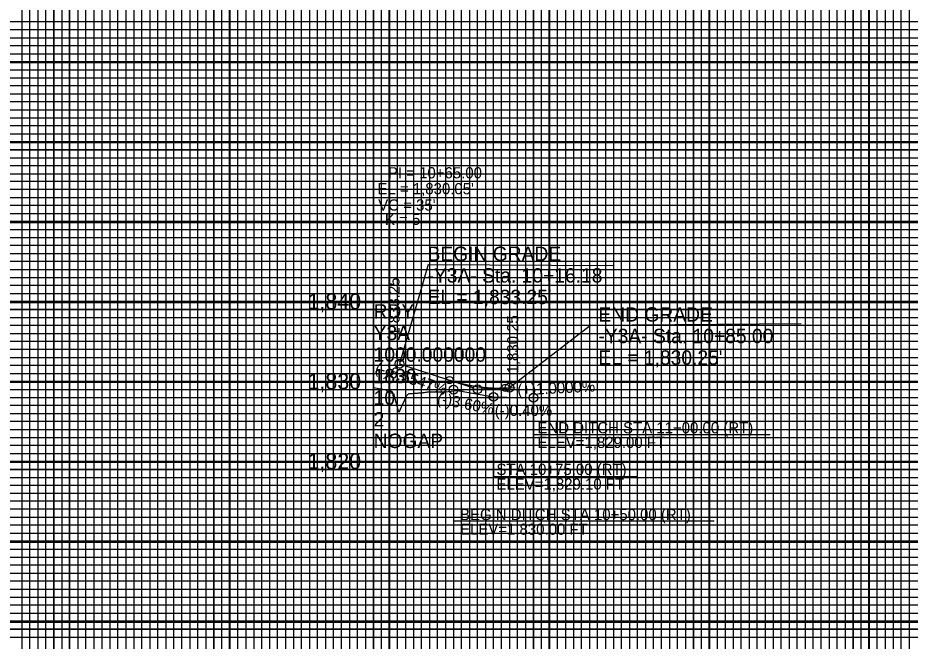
# Model space of a CAD drawing. Extents: x 553912 to 567693, y 512355 to 537539.
# Drawn here: x 560417 to 560975, y 521343 to 521733 of the extents above; entities that cross this region are included whole.
import ezdxf

# ---------------------------------------------------------------- set-up
doc = ezdxf.new("R2010")
doc.units = 0
for name, color, linetype in [('Exist Profile Cell', 7, 'Continuous'), ('Exist Vertical Profile Ground Line', 7, 'Continuous'), ('Exist Vertical Profile Vertical Axis Label', 7, 'Continuous'), ('Old_Level_42', 7, 'Continuous'), ('Old_Level_54', 7, 'Continuous'), ('Prop ROW Permanent Easement CELL', 7, 'Continuous'), ('Prop Vertical Profile Curve Label', 7, 'Continuous'), ('Prop Vertical Profile Ditch Grade Right', 7, 'Continuous'), ('Prop Vertical Profile Ditch Grade Right Label', 7, 'Continuous'), ('Prop Vertical Profile Grade', 7, 'Continuous'), ('Prop Vertical Profile Grade Label', 7, 'Continuous'), ('Prop VPI Label', 7, 'Continuous'), ('Sheet Profile Grid Major CELL', 7, 'Continuous'), ('Sheet Summary Guardrail CELL', 7, 'Continuous')]:
    doc.layers.add(name, color=color, linetype=linetype)

msp = doc.modelspace()

# ---------------------------------------------------------------- linework, layer by layer
at = {"layer": 'Exist Profile Cell'}
for q in [(560639.69, 521700.27), (560728.24, 521450.27), (560639.69, 521450.27)]:
    msp.add_line((560639.69, 521450.27), q, dxfattribs=at)
at = {"layer": 'Exist Vertical Profile Ground Line'}
msp.add_lwpolyline([(560639.69, 521501.61), (560645.54, 521500.52), (560647.01, 521500.28), (560648.88, 521498.77), (560652.04, 521497.86), (560655.11, 521487.07), (560655.61, 521486.15), (560656.47, 521488.01), (560657.15, 521489.49), (560657.83, 521490.97), (560658.5, 521492.45), (560659.18, 521493.93), (560659.86, 521495.41), (560660.54, 521496.6), (560661.59, 521497.76), (560661.9, 521497.79), (560662.58, 521497.84), (560663.26, 521497.9), (560663.94, 521497.95), (560664.62, 521498), (560665.3, 521498.05), (560665.97, 521498.1), (560666.65, 521498.15), (560667.33, 521498.19), (560668.01, 521498.24), (560668.69, 521498.28), (560669.37, 521498.32), (560670.34, 521498.38), (560670.73, 521498.44), (560671.41, 521498.55), (560672.09, 521498.66), (560672.76, 521498.77), (560673.44, 521498.88), (560674.12, 521498.97), (560674.8, 521498.98), (560675.48, 521498.98), (560676.16, 521498.98), (560676.84, 521498.98), (560677.52, 521498.98), (560678.2, 521498.98), (560678.88, 521498.98), (560679.56, 521498.98), (560680.23, 521498.98), (560680.91, 521498.98), (560681.59, 521498.98), (560682.27, 521498.98), (560682.95, 521498.98), (560683.63, 521498.98), (560684.44, 521498.97), (560699.56, 521500.58), (560700.04, 521500.58), (560700.64, 521500.64), (560710.34, 521500.79), (560717.31, 521500.81), (560717.75, 521500.78), (560718.51, 521500.82), (560728.24, 521501.54)], dxfattribs=at)
at = {"layer": 'Old_Level_42'}
for p, q in [((560439.66, 522125.42), (560439.66, 521100.42)), ((560489.66, 522125.42), (560489.66, 521100.42)), ((560539.66, 522125.42), (560539.66, 521100.42)), ((560589.66, 522125.42), (560589.66, 521100.42)), ((560639.66, 522125.42), (560639.66, 521100.42)), ((560689.66, 522125.42), (560689.66, 521100.42)), ((560739.66, 522125.42), (560739.66, 521100.42)), ((560789.66, 522125.42), (560789.66, 521100.42)), ((560839.66, 522125.42), (560839.66, 521100.42)), ((560889.66, 522125.42), (560889.66, 521100.42)), ((560939.66, 522125.42), (560939.66, 521100.42)), ((559939.66, 521700.42), (561439.66, 521700.42)), ((559939.66, 521650.42), (561439.66, 521650.42)), ((559939.66, 521600.42), (561439.66, 521600.42)), ((559939.66, 521550.42), (561439.66, 521550.42)), ((559939.66, 521500.42), (561439.66, 521500.42)), ((559939.66, 521450.42), (561439.66, 521450.42)), ((559939.66, 521400.42), (561439.66, 521400.42)), ((559939.66, 521350.42), (561439.66, 521350.42))]:
    msp.add_line(p, q, dxfattribs=at)
at = {"layer": 'Old_Level_54'}
for points in [[(560389.66, 522125.42), (560389.66, 521100.42), (560439.66, 521100.42), (560439.66, 522125.42)], [(560489.66, 522125.42), (560489.66, 521100.42), (560539.66, 521100.42), (560539.66, 522125.42)], [(560589.66, 522125.42), (560589.66, 521100.42), (560639.66, 521100.42), (560639.66, 522125.42)], [(560689.66, 522125.42), (560689.66, 521100.42), (560739.66, 521100.42), (560739.66, 522125.42)], [(560789.66, 522125.42), (560789.66, 521100.42), (560839.66, 521100.42), (560839.66, 522125.42)], [(560889.66, 522125.42), (560889.66, 521100.42), (560939.66, 521100.42), (560939.66, 522125.42)], [(561439.66, 521650.42), (559939.66, 521650.42), (559939.66, 521700.42), (561439.66, 521700.42)], [(561439.66, 521550.42), (559939.66, 521550.42), (559939.66, 521600.42), (561439.66, 521600.42)], [(561439.66, 521450.42), (559939.66, 521450.42), (559939.66, 521500.42), (561439.66, 521500.42)], [(561439.66, 521350.42), (559939.66, 521350.42), (559939.66, 521400.42), (561439.66, 521400.42)]]:
    msp.add_lwpolyline(points, dxfattribs=at)
at = {"layer": 'Prop ROW Permanent Easement CELL'}
for points in [[(560464.66, 522125.42), (560464.66, 521100.42), (560514.66, 521100.42), (560514.66, 522125.42)], [(560564.66, 522125.42), (560564.66, 521100.42), (560614.66, 521100.42), (560614.66, 522125.42)], [(560664.66, 522125.42), (560664.66, 521100.42), (560714.66, 521100.42), (560714.66, 522125.42)], [(560764.66, 522125.42), (560764.66, 521100.42), (560814.66, 521100.42), (560814.66, 522125.42)], [(560864.66, 522125.42), (560864.66, 521100.42), (560914.66, 521100.42), (560914.66, 522125.42)], [(560964.66, 522125.42), (560964.66, 521100.42), (561014.66, 521100.42)], [(561439.66, 521725.42), (559939.66, 521725.42), (559939.66, 521675.42), (561439.66, 521675.42)], [(561439.66, 521625.42), (559939.66, 521625.42), (559939.66, 521575.42), (561439.66, 521575.42)], [(561439.66, 521525.42), (559939.66, 521525.42), (559939.66, 521475.42), (561439.66, 521475.42)], [(561439.66, 521425.42), (559939.66, 521425.42), (559939.66, 521375.42), (561439.66, 521375.42)]]:
    msp.add_lwpolyline(points, dxfattribs=at)
at = {"layer": 'Prop Vertical Profile Curve Label'}
for centre in [(560687.19, 521506.26), (560722.19, 521501.4)]:
    msp.add_circle(centre, 2.25, dxfattribs=at)
at = {"layer": 'Prop Vertical Profile Ditch Grade Right'}
for p, q in [((560689.69, 521500.27), (560714.69, 521495.77)), ((560714.69, 521495.77), (560739.69, 521495.27))]:
    msp.add_line(p, q, dxfattribs=at)
at = {"layer": 'Prop Vertical Profile Ditch Grade Right Label'}
for p, q in [((560689.69, 521500.27), (560689.69, 521417.93)), ((560714.69, 521495.77), (560714.69, 521445.98)), ((560739.69, 521495.27), (560739.69, 521472.15)), ((560739.69, 521472.15), (560887.67, 521472.15)), ((560714.69, 521445.98), (560804.33, 521445.98)), ((560852.76, 521417.93), (560689.69, 521417.93))]:
    msp.add_line(p, q, dxfattribs=at)
for centre in [(560689.69, 521500.27), (560714.69, 521495.77), (560739.69, 521495.27)]:
    msp.add_circle(centre, 2.75, dxfattribs=at)
at = {"layer": 'Prop Vertical Profile Grade'}
for p, q in [((560655.87, 521516.52), (560687.19, 521506.26)), ((560722.19, 521501.4), (560724.69, 521501.52))]:
    msp.add_line(p, q, dxfattribs=at)
msp.add_spline([(560687.19, 521506.26), (560687.89, 521506.03), (560688.59, 521505.81), (560689.29, 521505.59), (560689.99, 521505.38), (560690.69, 521505.18), (560691.39, 521504.98), (560692.09, 521504.78), (560692.79, 521504.59), (560693.49, 521504.41), (560694.19, 521504.23), (560694.89, 521504.06), (560695.59, 521503.89), (560696.29, 521503.72), (560696.99, 521503.57), (560697.69, 521503.41), (560698.39, 521503.27), (560699.09, 521503.12), (560699.79, 521502.99), (560700.49, 521502.85), (560701.19, 521502.73), (560701.89, 521502.61), (560702.59, 521502.49), (560703.29, 521502.38), (560703.99, 521502.28), (560704.69, 521502.18), (560705.39, 521502.08), (560706.09, 521501.99), (560706.79, 521501.91), (560707.49, 521501.83), (560708.19, 521501.76), (560708.89, 521501.69), (560709.59, 521501.63), (560710.29, 521501.57), (560710.99, 521501.52), (560711.69, 521501.47), (560712.39, 521501.43), (560713.09, 521501.39), (560713.79, 521501.36), (560714.49, 521501.33), (560715.19, 521501.31), (560715.89, 521501.3), (560716.59, 521501.29), (560717.29, 521501.28), (560717.99, 521501.28), (560718.69, 521501.29), (560719.39, 521501.3), (560720.09, 521501.32), (560720.79, 521501.34), (560721.49, 521501.37), (560722.19, 521501.4)], degree=3, dxfattribs=at)
at = {"layer": 'Prop VPI Label'}
for p, q in [((560673.7, 521578.64), (560655.87, 521516.52)), ((560673.7, 521578.64), (560789.51, 521577.88)), ((560775.27, 521540.37), (560724.69, 521501.52)), ((560907.12, 521541.51), (560775.27, 521540.37)), ((560687.19, 521506.26), (560702.07, 521501.38)), ((560722.19, 521501.4), (560707.43, 521500.66))]:
    msp.add_line(p, q, dxfattribs=at)
for centre in [(560655.87, 521516.52), (560704.69, 521500.52), (560724.69, 521501.52)]:
    msp.add_circle(centre, 2.75, dxfattribs=at)
at = {"layer": 'Sheet Profile Grid Major CELL'}
for p, q in [((560449.45, 521054.67), (560449.45, 522254.67)), ((560549.45, 521054.67), (560549.45, 522254.67)), ((560649.45, 521054.67), (560649.45, 522254.67)), ((560749.45, 521054.67), (560749.45, 522254.67)), ((560849.45, 521054.67), (560849.45, 522254.67)), ((560949.45, 521054.67), (560949.45, 522254.67)), ((563849.45, 521704.67), (557249.45, 521704.67)), ((563849.45, 521654.67), (557249.45, 521654.67)), ((563849.45, 521604.67), (557249.45, 521604.67)), ((563849.45, 521554.67), (557249.45, 521554.67)), ((563849.45, 521504.67), (557249.45, 521504.67)), ((563849.45, 521454.67), (557249.45, 521454.67)), ((563849.45, 521404.67), (557249.45, 521404.67)), ((563849.45, 521354.67), (557249.45, 521354.67))]:
    msp.add_line(p, q, dxfattribs=at)
at = {"layer": 'Sheet Summary Guardrail CELL'}
for points in [[(560419.66, 522125.42), (560419.66, 521100.42), (560424.66, 521100.42), (560424.66, 522125.42)], [(560429.66, 522125.42), (560429.66, 521100.42), (560434.66, 521100.42), (560434.66, 522125.42)], [(560444.66, 522125.42), (560444.66, 521100.42), (560449.66, 521100.42), (560449.66, 522125.42)], [(560454.66, 522125.42), (560454.66, 521100.42), (560459.66, 521100.42), (560459.66, 522125.42)], [(560469.66, 522125.42), (560469.66, 521100.42)], [(560474.66, 522125.42), (560474.66, 521100.42), (560479.66, 521100.42), (560479.66, 522125.42), (560484.66, 522125.42), (560484.66, 521100.42), (560494.66, 521100.42), (560494.66, 522125.42), (560499.66, 522125.42), (560499.66, 521100.42), (560504.66, 521100.42), (560504.66, 522125.42), (560509.66, 522125.42), (560509.66, 521100.42)], [(560519.66, 521100.42), (560519.66, 522125.42)], [(560524.66, 522125.42), (560524.66, 521100.42), (560529.66, 521100.42), (560529.66, 522125.42)], [(560534.66, 522125.42), (560534.66, 521100.42), (560544.66, 521100.42), (560544.66, 522125.42)], [(560549.66, 522125.42), (560549.66, 521100.42), (560549.66, 521100.42), (560554.66, 521100.42), (560554.66, 522125.42)], [(560559.66, 522125.42), (560559.66, 521100.42), (560569.66, 521100.42), (560569.66, 522125.42)], [(560574.66, 522125.42), (560574.66, 521100.42), (560579.66, 521100.42), (560579.66, 522125.42)], [(560584.66, 522125.42), (560584.66, 521100.42), (560594.66, 521100.42), (560594.66, 522125.42)], [(560599.66, 522125.42), (560599.66, 521100.42), (560604.66, 521100.42), (560604.66, 522125.42)], [(560609.66, 522125.42), (560609.66, 521100.42), (560619.66, 521100.42), (560619.66, 522125.42)], [(560624.66, 522125.42), (560624.66, 521100.42), (560629.66, 521100.42), (560629.66, 522125.42)], [(560634.66, 522125.42), (560634.66, 521100.42), (560644.66, 521100.42), (560644.66, 522125.42)], [(560649.66, 522125.42), (560649.66, 521100.42), (560654.66, 521100.42), (560654.66, 522125.42)], [(560659.66, 522125.42), (560659.66, 521100.42), (560669.66, 521100.42), (560669.66, 522125.42)], [(560674.66, 522125.42), (560674.66, 521100.42), (560679.66, 521100.42), (560679.66, 522125.42)], [(560684.66, 522125.42), (560684.66, 521100.42), (560694.66, 521100.42), (560694.66, 522125.42)], [(560699.66, 522125.42), (560699.66, 521100.42)], [(560709.66, 522124.82), (560709.66, 521100.42), (560719.66, 521100.42), (560719.66, 522125.42)], [(560724.66, 522125.42), (560724.66, 521100.42), (560729.66, 521100.42), (560729.66, 522125.42)], [(560734.66, 522125.42), (560734.66, 521100.42), (560744.66, 521100.42), (560744.66, 522125.42)], [(560749.66, 522125.42), (560749.66, 521100.42), (560754.66, 521100.42), (560754.66, 522125.42)], [(560759.66, 522125.42), (560759.66, 521100.42), (560769.66, 521100.42), (560769.66, 522125.42)], [(560774.66, 522125.42), (560774.66, 521100.42), (560779.66, 521100.42), (560779.66, 522125.42)], [(560784.66, 522125.42), (560784.66, 521100.42), (560794.66, 521100.42), (560794.66, 522125.42)], [(560799.66, 522125.42), (560799.66, 521100.42), (560804.66, 521100.42), (560804.66, 522125.42)], [(560809.66, 522125.42), (560809.66, 521100.42), (560819.66, 521100.42), (560819.66, 522125.42)], [(560824.66, 522125.42), (560824.66, 521100.42), (560829.66, 521100.42), (560829.66, 522125.42)], [(560834.66, 522125.42), (560834.66, 521100.42), (560844.66, 521100.42), (560844.66, 522125.42)], [(560849.66, 522125.42), (560849.66, 521100.42), (560854.66, 521100.42), (560854.66, 522125.42)], [(560859.66, 522125.42), (560859.66, 521100.42), (560869.66, 521100.42), (560869.66, 522125.42)], [(560874.66, 522125.42), (560874.66, 521100.42), (560879.66, 521100.42), (560879.66, 522125.42)], [(560884.66, 522125.42), (560884.66, 521100.42), (560894.66, 521100.42), (560894.66, 522125.42)], [(560899.66, 522125.42), (560899.66, 521100.42), (560904.66, 521100.42), (560904.66, 522125.42)], [(560909.66, 522125.42), (560909.66, 521100.42), (560919.66, 521100.42), (560919.66, 522125.42)], [(560924.66, 522125.42), (560924.66, 521100.42), (560929.66, 521100.42), (560929.66, 522125.42)], [(560934.66, 522125.42), (560934.66, 521100.42), (560944.66, 521100.42), (560944.66, 522125.42)], [(560949.66, 522125.42), (560949.66, 521100.42), (560954.66, 521100.42), (560954.66, 522125.42)], [(560959.66, 522125.42), (560959.66, 521100.42), (560969.66, 521100.42), (560969.66, 522125.42)], [(560974.66, 522125.42), (560974.66, 521100.42), (560979.66, 521100.42)], [(560699.66, 521100.42), (560704.66, 521100.42), (560704.66, 522124.82)], [(561389.66, 521730.42), (559989.66, 521730.42), (559989.66, 521720.42), (561389.66, 521720.42)], [(561389.66, 521715.42), (559989.66, 521715.42), (559989.66, 521710.42), (561389.66, 521710.42)], [(561389.66, 521705.42), (559989.66, 521705.42), (559989.66, 521695.42), (561389.66, 521695.42)], [(561389.66, 521690.42), (559989.66, 521690.42), (559989.66, 521685.42), (561389.66, 521685.42)], [(561389.66, 521680.42), (559989.66, 521680.42), (559989.66, 521670.42), (561389.66, 521670.42)], [(561389.66, 521665.42), (559989.66, 521665.42), (559989.66, 521660.42), (561389.66, 521660.42)], [(561389.66, 521655.42), (559989.66, 521655.42), (559989.66, 521645.42), (561389.66, 521645.42)], [(561389.66, 521640.42), (559989.66, 521640.42), (559989.66, 521635.42), (561389.66, 521635.42)], [(561389.66, 521630.42), (559989.66, 521630.42), (559989.66, 521620.42), (561389.66, 521620.42)], [(561389.66, 521615.42), (559989.66, 521615.42), (559989.66, 521610.42), (561389.66, 521610.42)], [(561389.66, 521605.42), (559989.66, 521605.42)], [(559989.66, 521595.42), (561389.66, 521595.42)], [(561389.66, 521590.42), (559989.66, 521590.42), (559989.66, 521585.42), (561389.66, 521585.42)], [(561389.66, 521580.42), (559989.66, 521580.42), (559989.66, 521570.42), (561389.66, 521570.42)], [(561389.66, 521565.42), (559989.66, 521565.42), (559989.66, 521560.42), (561389.66, 521560.42)], [(561389.66, 521555.42), (559989.66, 521555.42), (559989.66, 521545.42), (561389.66, 521545.42)], [(561389.66, 521540.42), (559989.66, 521540.42), (559989.66, 521535.42), (561389.66, 521535.42)], [(561389.66, 521530.42), (559989.66, 521530.42), (559989.66, 521520.42), (561389.66, 521520.42)], [(561389.66, 521515.42), (559989.66, 521515.42), (559989.66, 521510.42), (561389.66, 521510.42)], [(561389.66, 521505.42), (559989.66, 521505.42), (559989.66, 521495.42), (561389.66, 521495.42)], [(561389.66, 521490.42), (559989.66, 521490.42), (559989.66, 521485.42), (561389.66, 521485.42)], [(561389.66, 521480.42), (559989.66, 521480.42), (559989.66, 521470.42), (561389.66, 521470.42)], [(561389.66, 521465.42), (559989.66, 521465.42), (559989.66, 521460.42), (561389.66, 521460.42)], [(561389.66, 521455.42), (559989.66, 521455.42), (559989.66, 521445.42), (561389.66, 521445.42)], [(561389.66, 521440.42), (559989.66, 521440.42), (559989.66, 521435.42), (561389.66, 521435.42)], [(561389.66, 521430.42), (559989.66, 521430.42), (559989.66, 521420.42), (561389.66, 521420.42)], [(561389.66, 521415.42), (559989.66, 521415.42), (559989.66, 521410.42), (561389.66, 521410.42)], [(561389.66, 521405.42), (559989.66, 521405.42), (559989.66, 521395.42), (561389.66, 521395.42)], [(561389.66, 521390.42), (559989.66, 521390.42), (559989.66, 521385.42), (561389.66, 521385.42)], [(561389.66, 521380.42), (559989.66, 521380.42), (559989.66, 521370.42), (561389.66, 521370.42)], [(561389.66, 521365.42), (559989.66, 521365.42), (559989.66, 521360.42), (561389.66, 521360.42)], [(561389.66, 521355.42), (559989.66, 521355.42), (559989.66, 521345.42), (561389.66, 521345.42)]]:
    msp.add_lwpolyline(points, dxfattribs=at)

# ---------------------------------------------------------------- texts
at = {"layer": 'Exist Profile Cell'}
for s, p in [('RDY', (560639.69, 521544.77)), ('Y3A', (560639.69, 521531.27)), ('1000.000000', (560639.69, 521517.77)), ('1830', (560639.69, 521504.27)), ('10', (560639.69, 521490.77)), ('2', (560639.69, 521477.27)), ('NOGAP', (560639.69, 521463.77))]:
    msp.add_text(s, height=9, dxfattribs=at).set_placement(p)
at = {"layer": 'Exist Vertical Profile Vertical Axis Label'}
for s, p in [('1,840', (560598.38, 521550.52)), ('1,830', (560598.38, 521500.52)), ('1,820', (560598.38, 521450.52))]:
    msp.add_text(s, height=10, dxfattribs=at).set_placement(p)
at = {"layer": 'Prop Vertical Profile Curve Label'}
for s, p in [("VC = 35'", (560642.56, 521612.33)), ('K = 5', (560646.76, 521603.38))]:
    msp.add_text(s, height=7, dxfattribs=at).set_placement(p)
at = {"layer": 'Prop Vertical Profile Ditch Grade Right'}
msp.add_text('(-)3.60%', height=7, rotation=348.6831, dxfattribs=at).set_placement((560678.99, 521491.67))
msp.add_text('(-)0.40%', height=7, dxfattribs=at).set_placement((560715.46, 521483.84))
at = {"layer": 'Prop Vertical Profile Ditch Grade Right Label'}
for s, p in [('END DITCH STA 11+00.00 (RT)', (560742.15, 521472.96)), ('ELEV=1,829.00 FT', (560742.15, 521463.79)), ('STA 10+75.00 (RT)', (560716.5, 521446.93)), ('ELEV=1,829.10 FT', (560716.5, 521437.75)), ('BEGIN DITCH STA 10+50.00 (RT)', (560693.73, 521418.66)), ('ELEV=1,830.00 FT', (560693.73, 521409.48))]:
    msp.add_text(s, height=7, rotation=360, dxfattribs=at).set_placement(p)
at = {"layer": 'Prop Vertical Profile Grade Label'}
for s, rotation, p in [('(-)6.5547%', 341.8542, (560640.1, 521511.17)), ('(+)1.0000%', 2.8624, (560729.76, 521496.66))]:
    msp.add_text(s, height=7, rotation=rotation, dxfattribs=at).set_placement(p)
at = {"layer": 'Prop VPI Label'}
for s, height, p in [('PI = 10+65.00', 7, (560648.63, 521632.49)), ("EL = 1,830.05'", 7, (560642.06, 521622.54)), ('BEGIN GRADE ', 9, (560673.39, 521580.79)), ('-Y3A- Sta. 10+16.18', 9, (560673.39, 521567.29)), ("EL = 1,833.25'", 9, (560673.39, 521553.79)), ('END GRADE ', 9, (560780.29, 521542.87)), ('-Y3A- Sta. 10+85.00', 9, (560780.29, 521529.37)), ("EL = 1,830.25'", 9, (560780.29, 521515.87))]:
    msp.add_text(s, height=height, dxfattribs=at).set_placement(p)
for s, p in [('1,833.25', (560655.87, 521534.02)), ('1,830.25', (560730.19, 521510.41))]:
    msp.add_text(s, height=7, rotation=90, dxfattribs=at).set_placement(p)

doc.saveas('drawing.dxf')
